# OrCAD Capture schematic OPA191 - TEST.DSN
size A
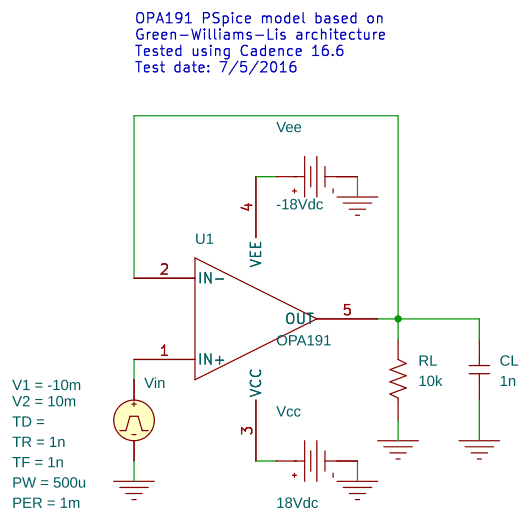
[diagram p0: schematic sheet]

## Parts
CL  1n  [RAD/CK05]
RL  10k  [AX/RC05]
U1  OPA191
Vcc  VDC
Vee  VDC
Vin  VPULSE

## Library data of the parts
CL = C
RL = R
U1 = OPA191_3
Vcc = VDC: DC: 18Vdc
Vee = VDC: DC: -18Vdc
Vin = VPULSE: PER: 1m; PW: 500u; TF: 1n; TR: 1n; V1: -10m; V2: 10m

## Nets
0: CL.1 RL.1 Vcc.1(-) Vee.1(-) Vin.2(-)
N02388: CL.2 RL.2 U1.2(IN-) U1.5(OUT)
N02583: U1.4(VEE) Vee.0(+)
N02769: U1.1(IN+) Vin.1(+)
N03076: U1.3(VCC) Vcc.0(+)

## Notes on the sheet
- OPA191 PSpice model based on
  Green-Williams-Lis architecture
  Tested using Cadence 16.6
  Test date: 7/5/2016
